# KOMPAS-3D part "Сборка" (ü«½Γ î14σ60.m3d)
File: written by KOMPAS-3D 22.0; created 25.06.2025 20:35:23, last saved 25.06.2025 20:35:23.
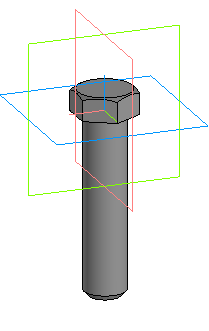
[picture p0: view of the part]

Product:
- Component [detail]: Болт М14x60 ГОСТ 15591-70  | qty 1  | source file: Болт М14x60 ГОСТ 15591-70.m3d
- Part/product: Сборка

Referenced files in D:\MY\WORK\MPEI\ППЭ_2025-2026\Варианты\Стандартные детали\: Болт М14x60 ГОСТ 15591-70.m3d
